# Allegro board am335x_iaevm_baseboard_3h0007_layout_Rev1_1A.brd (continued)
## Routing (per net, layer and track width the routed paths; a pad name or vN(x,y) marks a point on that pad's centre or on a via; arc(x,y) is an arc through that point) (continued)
DDR_D8: length 46.2
  TOP w0.076: v1(97.96,57.44) U31.C8
  TOP w0.121: v1(88.43,66.55) 88.18,66.8 88.18,67.47 86.33,69.32 86.33,70.33 85.95,70.72 85.95,71.02 85.7,71.27 85.7,71.41 R529.2
  BOTTOM w0.076: 100.14,62.84 98.65,62.84 98.39,62.58 98.39,62.08 98.18,61.87 97.07,61.87 96.79,61.59 96.79,61.28 96.94,61.14 96.94,60.49 96.81,60.36 96.11,60.36 95.99,60.24 95.99,59.7 96.11,59.57 96.87,59.57 97,59.45 97,59.18 96.87,59.05 96.05,59.05 95.92,58.93 95.92,58.52 96.05,58.39 96.43,58.39 96.56,58.27 96.56,57.19 96.74,57 97.53,57 v1(97.96,57.44)
  BOTTOM w0.121: v1(88.43,66.55) 88.64,66.34 90.42,66.34 90.63,66.13 96.24,66.13 96.44,66.33 101.89,66.33 102.02,66.2 102.02,59.73 101.89,59.6 100.81,59.6 100.68,59.73 100.68,62.58 100.43,62.84 100.14,62.84
DDR_D9: length 46.2
  TOP w0.076: 100.14,64.48 100.03,64.48 100.01,64.46 96.49,64.46 96.37,64.33 96.37,63.16 96.49,63.03 97.4,63.03 97.52,62.9 97.52,62.67 U31.C2
  TOP w0.121: v1(86.97,70.45) 86.85,70.45 86.47,70.83 86.47,70.84 86.21,71.1 86.21,71.34 85.95,71.6 R530.2 ; 100.14,64.48 100.24,64.48 100.36,64.36 102.74,64.36 102.86,64.49 102.86,65.68 102.74,65.81 101.65,65.81 101.15,66.32 101.15,67.54 101.02,67.66 98.33,67.66 98.2,67.54 98.2,65.91 98.02,65.73 98.02,65.57 97.89,65.45 96.3,65.45 96.18,65.57 96.18,66.2 97,67.03 97,68.43 97.13,68.55 101.13,68.55 101.26,68.68 v1(101.26,69.06)
  BOTTOM w0.121: v1(101.26,69.06) 101.26,69.33 101.13,69.45 95.84,69.45 95.55,69.16 93.32,69.16 92.91,69.16 92.28,69.79 91.48,69.79 89.11,69.79 88.96,69.94 87.87,69.94 87.54,70.27 87.15,70.27 v1(86.97,70.45)
DDR_D10: length 42.5
  TOP w0.076: 100.01,59.41 96.89,59.41 96.76,59.28 U31.D7
  TOP w0.121: v1(88.3,70.4) 87.73,70.4 87.16,70.97 87.16,71.41 86.91,71.67 R531.2 ; 100.01,59.41 101.82,59.41 101.95,59.28 101.95,56.62 102.08,56.49 102.93,56.49 103.05,56.62 103.05,62.62 103.18,62.75 103.48,62.75 103.61,62.87 103.61,66.43 103.48,66.55 102.02,66.55 101.89,66.68 101.89,68.43 102.02,68.55 102.34,68.55 102.46,68.68 102.46,68.88 v1(102.41,68.93)
  BOTTOM w0.121: v1(102.41,68.93) 102.41,69.38 102.28,69.51 101.83,69.51 101.83,69.51 101.66,69.51 101.29,69.89 99.92,69.89 99.73,69.7 95.73,69.7 95.44,69.41 93.22,69.41 93.01,69.41 92.38,70.04 91.58,70.04 89.23,70.04 88.88,70.38 88.62,70.38 88.61,70.4 v1(88.3,70.4)
DDR_D11: length 43.7
  TOP w0.076: v1(97.16,61.44) U31.D3
  LY3 w0.133: v1(85.81,70.09) 85.54,70.09 84.24,71.39 84.24,73.02 84.05,73.21 v1(84.05,73.95)
  BOTTOM w0.076: v1(97.16,61.44) 97.16,60.33 97.43,60.06 100.06,60.06
  BOTTOM w0.121: 100.06,60.06 100.14,59.98 100.14,58.65 100.26,58.52 103.29,58.52 103.42,58.65 103.42,68.49 103.29,68.62 102.72,68.62 102.59,68.49 100.94,68.49 100.81,68.62 100.81,69.08 100.68,69.21 95.94,69.21 95.65,68.92 94.38,68.92 93.43,68.92 92.81,68.92 92.18,69.55 91.38,69.55 89.01,69.55 88.86,69.7 87.73,69.7 87.42,70.01 85.89,70.01 v1(85.81,70.09) ; R532.2 v1(84.05,73.95)
DDR_D12: length 44.2
  TOP w0.076: 100.14,64.24 97.29,64.24 97.16,64.11 v1(97.16,63.84) U31.D1
  TOP w0.121: v1(96.62,65.89) 97.83,65.89 97.95,66.01 97.95,67.79 98.08,67.92 101.27,67.92 101.4,67.79 101.4,66.42 101.76,66.06 102.98,66.06 103.11,65.93 103.11,63.37 102.98,63.24 102.97,63.24 102.85,63.11 102.56,62.82 102.56,60.55 102.43,60.43 100.43,60.43 100.3,60.55 100.3,64.07 100.14,64.24 100.14,64.24 ; v1(88.49,65.89) 88.47,65.89 87.93,66.43 87.93,67.27 85.38,69.82 85.38,69.89 85.37,69.9 85.37,70.27 85.38,70.28 85.38,70.71 v1(85.51,70.84)
  BOTTOM w0.121: v1(88.49,65.89) 89.15,65.89 89.35,66.09 90.32,66.09 90.52,65.89 v1(96.62,65.89) ; R533.2 85.51,74.21 85.51,70.84 v1(85.51,70.84)
DDR_D13: length 46.5
  TOP w0.076: v1(97.16,56.64) U31.D9
  TOP w0.121: v1(100.75,56.68) 100.75,55.79 100.88,55.66 103.67,55.66 103.8,55.79 103.8,61.82 103.92,61.95 104.24,61.95 104.37,62.08 104.37,67.47 104.24,67.6 v1(102.97,67.6)
  LY3 w0.133: v1(87.18,69.48) 87.18,69.72 87.42,69.95 87.42,70.63 87.15,70.9 87.04,70.9 v1(86.65,71.28)
  BOTTOM w0.076: 99.11,56.36 99.19,56.44 99.19,56.83 99.36,57 100.13,57 100.14,57 ; 98.41,56.36 98.33,56.44 98.33,56.81 98.14,57 97.81,57 97.44,56.64 v1(97.16,56.64)
  BOTTOM w0.121: R534.2 86.84,74.65 86.4,74.21 86.4,73.82 86.14,73.57 86.14,71.79 v1(86.65,71.28) ; 100.14,57 100.43,57 v1(100.75,56.68) ; v1(102.97,67.6) 102.97,68.12 102.84,68.24 100.84,68.24 100.12,68.96 96.05,68.96 95.76,68.67 94.48,68.67 93.53,68.67 92.71,68.67 92.08,69.3 91.27,69.3 88.91,69.3 88.76,69.45 87.21,69.45 v1(87.18,69.48) ; 98.41,56.36 98.58,56.19 98.94,56.19 99.11,56.36
DDR_D14: length 40.3
  TOP w0.076: 100.02,60.84 100.02,62.68 99.67,63.03 98.72,63.03 98.36,63.39 U31.B1
  TOP w0.121: v1(101.2,70.66) 101.7,70.66 101.83,70.53 101.83,68.71 101.64,68.53 101.64,66.52 101.86,66.31 103.23,66.31 103.36,66.18 103.36,63.12 103.23,62.99 103.08,62.99 102.95,62.87 102.81,62.72 102.81,60.24 102.68,60.11 100.14,60.11 100.02,60.24 100.02,60.84
  BOTTOM w0.121: R535.2 87.09,72.24 87.09,71.17 87.42,70.84 87.79,70.84 87.79,70.85 88.79,70.85 89.35,70.29 91.68,70.29 91.69,70.29 92.17,70.29 92.49,70.29 92.68,70.09 93.12,69.66 95.06,69.66 95.35,69.95 96.62,69.95 96.75,70.08 96.75,70.73 96.87,70.85 97.26,70.85 97.38,70.73 97.38,70.08 97.51,69.95 97.89,69.95 98.02,70.08 98.02,70.73 98.14,70.85 98.65,70.85 98.78,70.73 98.78,70.08 98.91,69.95 99.22,69.95 99.35,70.08 99.35,70.73 99.48,70.85 101,70.85 v1(101.2,70.66)
DDR_D15: length 40
  TOP w0.076: v1(98.76,56.64) U31.B9
  TOP w0.121: R536.2 90.27,71.6 90.65,71.6 v1(90.97,71.28)
  BOTTOM w0.076: 100.14,57.39 99.38,57.39 99.19,57.21 99.19,57.07 v1(98.76,56.64)
  BOTTOM w0.121: v1(90.97,71.28) 91.22,71.03 92.79,71.03 93.43,70.4 94.28,70.4 94.57,70.69 95.52,70.69 96.43,71.6 101.89,71.6 103.66,69.83 103.66,55.34 103.42,55.09 101.57,55.09 101.45,55.22 101.45,58.1 101.32,58.23 100.49,58.23 100.37,58.1 100.37,57.52 100.24,57.39 100.14,57.39
DDR_DQM0: length 41
  TOP w0.076: 77.91,61.27 77.7,61.06 76.68,61.06 76.54,61.21 v1(76.54,61.44) U8.B3
  TOP w0.121: v1(90.02,67.04) 90.02,67.6 89.57,68.05 89.57,68.43 89.7,68.55 90.14,68.55 90.27,68.68 90.27,68.87 90.14,69 89.7,69 89.57,69.13 89.57,69.92 90.05,70.4 90.46,70.4 90.59,70.27 90.59,69.44 90.72,69.32 90.94,69.32 91.41,69.79 91.41,71.41 91.41,71.41 91.41,71.47 91.15,71.73 91.1,71.73 R16.2 ; v1(76.18,67.15) 76.17,67.16 76.17,68.36 76.05,68.49 75.79,68.49 75.66,68.36 75.66,67.87 75.48,67.68 75.48,66.14 75.67,65.94 77.23,65.94 78.01,65.16 78.01,64.62 78.02,64.62 78.02,64.11 78.14,63.99 78.6,63.99 78.72,63.87 78.72,63.62 78.6,63.5 78.14,63.5 78.02,63.38 78.02,63.14 78.14,63.02 78.6,63.02 78.72,62.9 78.72,62.66 78.6,62.54 78.14,62.54 78.02,62.42 78.02,61.38 77.91,61.27
  BOTTOM w0.121: v1(90.02,67.04) 89.83,66.85 89.5,66.85 89.5,66.84 89.14,66.84 88.69,67.28 86.53,67.28 85.9,67.91 83.9,67.91 80.2,67.91 79.21,66.92 77.68,66.92 77.57,67.03 77.57,67.22 77.44,67.34 77.25,67.34 77.13,67.22 77.13,67.05 77,66.92 76.81,66.92 76.58,67.15 v1(76.18,67.15)
DDR_DQM1: length 46.2
  TOP w0.076: v1(98.76,61.44) U31.B3
  BOTTOM w0.076: v1(98.76,61.44) 99.03,61.44 99.16,61.56 99.16,62.46 99.29,62.58 100.14,62.58
  BOTTOM w0.121: 100.14,62.58 100.26,62.58 100.38,62.46 100.38,58.9 100.51,58.77 102.15,58.77 102.27,58.9 102.27,60.62 102.4,60.74 102.59,60.74 102.72,60.62 102.72,58.9 102.84,58.77 103.03,58.77 103.16,58.9 103.16,67.03 103.03,67.16 102.53,67.16 102.4,67.28 102.4,67.79 102.21,67.98 100.75,67.98 100.74,67.99 100.73,67.99 100.02,68.71 96.15,68.71 95.86,68.42 94.59,68.42 93.63,68.42 92.6,68.42 91.97,69.05 91.05,69.05 88.75,69.05 88.6,69.2 87.53,69.2 87.36,69.03 87,69.03 86.39,69.64 85.32,69.64 85,69.96 R19.2
DDR_DQS0: length 37.8
  TOP w0.076: U8.B7 76.66,59.16 77.78,59.16
  TOP w0.121: v1(79.98,66.65) 79.98,66.2 80.43,65.75 80.43,65.29 80.44,65.28 80.44,65.22 80.62,65.04 80.62,62.07 80.3,61.76 80.3,55.95 79.82,55.47 79.41,55.47 79.29,55.6 79.29,56.11 79.16,56.23 78.28,56.23 78.16,56.36 78.16,57.11 77.91,57.36 77.91,59.03 77.78,59.16 ; R17.2 93.57,71.5 93.18,71.11 93.18,68.99 91.92,67.74 v1(91.92,66.9)
  BOTTOM w0.121: v1(91.92,66.9) 91.54,66.52 90.66,66.52 90.59,66.59 89.03,66.59 88.6,67.03 86.43,67.03 85.79,67.66 81,67.66 v1(79.98,66.65)
DDR_DQS1: length 42.6
  TOP w0.121: U31.B7 98.21,58.64 98.08,58.76 98.08,59.03 98.21,59.16 101.57,59.16 101.7,59.03 101.7,56.36 101.83,56.23 103.17,56.23 103.3,56.36 103.3,62.15 103.7,62.55 103.74,62.55 103.87,62.68 103.87,66.78 103.74,66.91 102.42,66.91 102.15,67.18 102.15,68.02 102.42,68.29 102.72,68.29 102.85,68.42 102.85,69.13 102.65,69.32 v1(102.65,69.76) ; v1(87.6,71.28) 87.86,71.54 R20.2
  BOTTOM w0.121: v1(102.65,69.76) 101.76,69.76 101.64,69.89 101.64,70.97 101.51,71.1 96.63,71.1 95.73,70.2 94.77,70.2 94.48,69.91 93.22,69.91 92.93,70.2 92.59,70.54 92.07,70.54 89.45,70.54 88.89,71.1 88.18,71.1 88,71.28 v1(87.6,71.28)
DDR_DQSN0: length 40.1
  TOP w0.076: 77.9,56.87 U8.A8
  TOP w0.121: 77.9,56.87 77.91,56.86 77.91,55.7 78.4,55.22 79.92,55.22 80.56,55.85 80.56,61.63 80.86,61.94 80.86,65.14 80.69,65.32 80.69,65.39 80.68,65.39 80.68,66.27 80.42,66.52 80.42,66.83 80.09,67.17 79.4,67.17 78.59,67.98 v1(78.58,67.98) ; v1(92.43,67.6) 93.43,68.6 93.43,71 93.82,71.4 93.82,71.4 94.53,72.11 R539.2
  BOTTOM w0.121: v1(78.58,67.98) 78.59,67.98 79.27,68.67 86.2,68.67 86.82,68.05 89.64,68.05 89.9,67.78 90.3,67.78 90.48,67.6 v1(92.43,67.6)
DDR_DQSN1: length 41.4
  TOP w0.121: v1(102.27,70.46) 102.96,70.46 103.1,70.32 103.1,68.17 102.97,68.04 102.53,68.04 102.4,67.92 102.4,67.28 102.53,67.16 103.99,67.16 104.11,67.03 104.11,62.43 103.99,62.31 103.8,62.31 103.55,62.05 103.55,56.11 103.42,55.98 101.45,55.98 101.32,56.11 101.32,58.71 101.19,58.84 100.39,58.84 100.27,58.71 100.27,58.09 100.01,57.84 v1(99.69,57.84) U31.A8 ; R540.2 89.05,72.11 89.29,71.87 v1(89.29,71.53)
  BOTTOM w0.121: v1(89.29,71.53) 89.29,71.12 89.63,70.79 92.69,70.79 93.18,70.3 93.32,70.15 94.38,70.15 94.67,70.45 95.62,70.45 96.52,71.35 101.76,71.35 101.89,71.22 101.89,70.59 102.02,70.46 v1(102.27,70.46)
DDR_ODT: length 65.1
  TOP w0.076: U31.F9 95.16,56.36 ; v1(72.49,56.68) 72.58,56.68 U8.F9
  TOP w0.121: 95.16,56.36 v1(95.16,55.73) ; R543.2 82.78,71.47 83.35,71.47 83.86,70.97 83.86,69.89 87.19,66.56 87.19,66.01 87.38,65.82 87.38,62.96 86.13,61.71 86.13,56.89 85.91,56.66 85.91,55.11 84.72,53.92 84.34,53.92 84.11,53.69 v1(84.11,53.11)
  BOTTOM w0.121: v1(72.49,56.68) 71.73,56.68 71.6,56.55 71.6,51.47 71.73,51.35 83.29,51.35 83.41,51.47 83.41,52.81 83.71,53.11 v1(84.11,53.11) 84.57,53.11 84.81,52.87 84.81,50.71 84.94,50.58 95.35,50.58 95.48,50.71 95.48,54.08 95.6,54.2 95.99,54.2 96.11,54.33 96.11,55.52 95.91,55.73 v1(95.16,55.73)
DDR_RASN: length 63.5
  TOP w0.076: v1(72.54,59.04) U8.F7 ; v1(94.76,59.04) U31.F7
  LY3 w0.133: v1(84.49,57) 84.84,57 85.32,57.47 85.32,58.71 85.13,58.9 84.75,58.9 84.49,59.16 84.49,59.53 84.5,59.54 84.5,59.79 84.68,59.98 84.86,59.98 85.12,60.24 85.12,62.19 85.51,62.58 85.51,66.71 80.62,71.6 80.62,73 79.79,73.82 v1(79.73,73.82)
  BOTTOM w0.076: 90.59,56.79 90.59,57.7 90.72,57.82 94.17,57.82 94.33,57.99 94.33,58.91 94.46,59.04 v1(94.76,59.04) ; v1(72.54,59.04) 72.24,59.04 72.11,59.16 72.11,60.15 72.24,60.27 73.63,60.27 73.76,60.15 73.76,58.9 73.89,58.77 76.05,58.77 77.12,57.7 77.91,57.7
  BOTTOM w0.121: v1(79.73,73.82) 79.79,73.82 80.24,74.27 R14.2 ; 84.49,57 v1(84.49,57) ; 84.49,57 85.37,57 85.38,56.99 86.49,56.99 86.68,56.8 86.72,56.8 86.75,56.77 87.02,56.77 87.29,56.5 87.29,54.33 87.41,54.2 92.11,54.2 92.24,54.33 92.24,54.59 92.11,54.72 90.87,54.72 90.59,54.99 90.59,56.79 ; 84.49,57 84.49,57.19 84.37,57.32 83.99,57.32 83.79,57.12 83.61,57.12 83.41,57.32 83.16,57.32 83.04,57.2 83.04,56.92 82.92,56.8 82.68,56.8 82.56,56.92 82.56,57.2 82.44,57.32 82.2,57.32 82.08,57.2 82.08,56.92 81.96,56.8 81.72,56.8 81.6,56.92 81.6,57.2 81.48,57.32 81.23,57.32 81.11,57.2 81.11,56.92 80.99,56.8 80.75,56.8 80.63,56.92 80.63,57.2 80.51,57.32 80.27,57.32 80.15,57.2 80.15,56.92 80.03,56.8 79.79,56.8 79.67,56.92 79.67,57.2 79.55,57.32 79.3,57.32 79.18,57.2 79.18,56.92 79.06,56.8 78.58,56.8 78.33,57.05 78.33,57.5 78.13,57.7 77.91,57.7
DDR_VREF: length 67
  TOP w0.076: 95.16,65.16 95.16,63.61 95.29,63.49 95.4,63.49 95.96,62.93 U31.E2 v1(96.36,62.24) ; v1(74.14,62.24) U8.E2 73.75,62.64 74.21,63.09 74.21,64.81 74.08,64.93 73.06,64.93 72.94,65.06 72.94,65.16
  TOP w0.102: v2(84.2,80.2) U2.J4
  TOP w0.121: v1(73.44,67.16) 72.94,66.65 72.94,65.16 ; 95.16,65.16 95.16,66.03 94.28,66.91 94.28,66.96 R542.2
  BOTTOM w0.076: v1(74.14,62.24) 74.55,61.82 77.57,61.82 77.89,61.5 77.91,61.5 ; 89.24,59.41 92.8,59.41 92.94,59.56 94.67,59.56 95.16,60.04 95.16,61.7 95.33,61.87 95.99,61.87 v1(96.36,62.24)
  BOTTOM w0.102: 77.19,80.44 77.96,81.21 79.53,81.21 79.7,81.38 80.43,81.38 81.19,80.62 83.52,80.62 83.94,80.2 v2(84.2,80.2) 84.59,80.2 R541.2
  BOTTOM w0.121: 89.24,59.41 89.02,59.41 88.17,60.26 88.17,60.48 87.66,60.99 82.47,60.99 81.71,61.75 81.02,61.75 80.77,61.49 79.22,61.49 79.09,61.63 78.72,61.63 78.59,61.5 77.91,61.5 ; v1(73.44,67.16) 71.83,68.77 71.83,73.86 72.23,74.27 72.23,77.25 71.6,77.88 71.6,78.67 72.79,79.85 74.01,79.85 74.06,79.9 76.16,79.9 76.36,80.09 76.84,80.09 77.18,80.44 77.19,80.44
DDR_WEN: length 60.6
  TOP w0.076: v1(72.54,61.44) 72.49,61.39 72.49,60.87 72.59,60.77 73.55,60.77 73.66,60.87 73.66,61.06 73.53,61.19 73.06,61.19 72.94,61.31 U8.F3 ; U31.F3 v1(95.56,61.44)
  TOP w0.121: R15.2 73.57,71.56 75.37,69.77 77.47,69.77 79.67,67.56 79.82,67.42 80.19,67.42 80.67,66.93 80.67,66.63 81.57,65.73 81.57,65.32 81.55,65.31 81.55,61.25 81.32,61.01 v1(81.32,61)
  BOTTOM w0.076: 89.3,57.31 89.59,57.31 89.7,57.43 89.7,59.09 89.83,59.22 90.98,59.22 91.11,59.09 91.11,58.79 91.24,58.67 91.71,58.67 91.78,58.74 92.11,58.74 92.18,58.67 92.51,58.67 92.73,58.88 92.73,59.12 93.01,59.4 93.31,59.4 93.46,59.26 93.66,59.26 93.81,59.4 94.11,59.4 94.26,59.26 94.46,59.26 94.61,59.4 95.73,59.4 95.83,59.5 95.83,61.33 95.73,61.44 v1(95.56,61.44) ; 77.91,61.06 77.91,59.85 77.79,59.73 77.63,59.73 77.51,59.85 77.51,60.74 77.38,60.87 77.19,60.87 77.08,60.76 77.08,59.85 76.95,59.73 76.36,59.73 76.24,59.85 76.24,60.04 76.11,60.17 75.92,60.17 75.79,60.04 75.79,59.85 75.67,59.73 74.97,59.73 74.84,59.85 74.84,60.18 74.8,60.22 74.8,60.25 74.5,60.55 74.5,61.59 74.29,61.8 73.82,61.8 73.7,61.93 73.7,62.46 73.57,62.58 73.38,62.58 73.25,62.46 73.25,61.31 73.13,61.19 72.78,61.19 v1(72.54,61.44)
  BOTTOM w0.121: 77.91,61.06 78.04,61.19 78.28,61.19 78.52,60.94 78.52,60.35 78.7,60.17 79.16,60.17 79.29,60.3 79.29,60.87 79.42,61 80.04,61 80.17,60.87 80.17,60.55 80.3,60.43 80.49,60.43 80.62,60.55 80.62,60.87 80.75,61 v1(81.32,61) 81.32,60.56 81.44,60.43 86.97,60.43 87.55,59.86 88.22,59.86 88.55,59.53 88.55,59.25 89.13,58.68 89.13,57.49 89.3,57.31
EMU2: length 53.9
  TOP w0.121: R76.1 66.18,94.02 65.73,94.46 64.94,94.46 64.12,95.29 60.34,95.29 59.49,94.44 57.37,94.44 56.03,93.11 48.22,93.11 47.24,92.13 32.7,92.13 31.75,91.19 27.94,91.19 26.58,89.83 21.63,89.83 v1(21.12,89.32) ; 24,86.65 v1(22.14,86.65)
  BOTTOM w0.121: v1(21.12,89.32) 21.12,87.13 21.6,86.65 v1(22.14,86.65)
EMU3: length 40.2
  TOP w0.121: J2.18 31.66,86.65 32.04,87.03 32.04,89.78 33.27,91 35.21,91 35.62,90.59 46.9,90.59 48.68,92.37 57.23,92.37 57.31,92.45 61.59,92.45 62.71,93.57 63.48,93.57 R77.1
EMU4: length 62.5
  TOP w0.121: 24,85.38 v1(22.14,85.38) ; v1(20.1,89.32) 20.87,88.56 26.2,88.56 27.47,89.83 31.53,89.83 32.96,91.25 47.19,91.25 48.55,92.61 56.24,92.61 57.19,93.57 59.22,93.57 59.73,93.06 61.31,93.06 62.39,94.14 63.86,94.14 64.57,93.44 64.96,93.44 65.65,92.75 67.66,92.75 68.42,91.99 70.52,91.99 R78.1
  BOTTOM w0.121: v1(20.1,89.32) 20.1,86.65 21.37,85.38 v1(22.14,85.38)
EMU_RSTN: length 6.4
  TOP w0.121: R517.1 v1(22.14,87.92) 24,87.92
  BOTTOM w0.121: v1(22.14,87.92) 22.77,87.92 23.15,87.54 23.15,87.03 23.53,86.65 C260.1
ENZ_KALDO_1P8V: length 9.6
  TOP w0.102: U2.B4 78.64,80.24 78.64,79.72 78.33,79.41 77.76,79.41 77.34,79.83
  TOP w0.121: 77.34,79.83 76.63,79.83 75.97,79.17 72,79.17 R48.2
EXP0_P25: length 5.4
  BOTTOM w0.121: R178.2 132.45,92.79 133.86,92.79 133.93,92.72 134.63,92.72 J3.25
EXP3_P9: length 2.8
  BOTTOM w0.121: J6.9 TP35.1
EXP_ECAP0_IN_PWM0_OUT: length 4.1
  TOP w0.121: R210.2 v1(74.33,134.02)
  BOTTOM w0.121: v1(74.33,134.02) 73.57,134.78 J5.19
EXP_GPMC_ADVN_ALE: length 17.1
  TOP w0.121: R182.1 138.21,97.45 138.21,96.3 137.18,95.27 132.59,95.27 131.82,94.49 131.82,93.97 131.61,93.77 129.81,93.77 128.8,94.78 127.81,94.78 126.93,93.89 J4.26
EXP_GPMC_BE0N_CLE: length 15.7
  TOP w0.121: R184.1 138.08,94.78 132.8,94.78 132.31,94.29 132.31,93.58 131.61,92.87 v1(130.26,92.87)
  BOTTOM w0.121: J4.28 126.66,91.35 127.67,92.37 129.4,92.37 129.78,92.75 130.13,92.75 v1(130.26,92.87)
EXP_GPMC_BE1N: length 8.8
  TOP w0.121: J5.2 99.27,139.61 99.4,139.74 99.4,141.13 99.27,141.26 96.56,141.26 96.43,141.39 R186.1
EXP_GPMC_CLK: length 8.8
  TOP w0.121: 119.93,95.03 123.55,95.03 124.04,95.52 126.4,95.52 127.31,96.43 J4.23
EXP_GPMC_CS0N: length 13.1
  TOP w0.121: J4.25 129.33,93.89 129.7,93.52 131.9,93.52 132.06,93.68 132.06,94.39 132.69,95.02 137.31,95.02 138.47,96.18 138.47,96.43 R183.1
EXP_GPMC_CS3N: length 8.8
  TOP w0.121: R187.1 v1(93.89,142)
  BOTTOM w0.121: J5.4 93.89,140.68 93.76,140.8 92.14,140.8 92.01,140.93 92.01,142.99 92.14,143.12 93.76,143.12 93.89,142.99 v1(93.89,142)
EXP_GPMC_OEN_REN: length 79.4
  TOP w0.121: v1(137.58,104.56) 137.96,104.18 R189.1 ; J5.6 92.61,138.35 97.42,138.35 97.54,138.47 99.48,138.47 100.06,137.88 106.29,137.88 109.89,134.28 118.78,134.28 120.18,132.88 129.83,132.88 131.61,131.1 134.69,131.1 136.73,129.06 137.1,129.06 137.64,128.52 137.64,128.06 138.03,127.67 v1(139.23,127.67)
  BOTTOM w0.121: v1(137.58,104.56) 137.58,104.81 138.34,105.57 138.34,109.18 137.45,110.06 137.45,117.59 138.09,118.23 138.09,126.23 138.34,126.48 138.34,126.78 v1(139.23,127.67)
EXP_GPMC_WAIT: length 13.9
  TOP w0.121: J4.19 130.21,101.51 132.24,103.54 132.24,104.43 132.75,104.94 136.17,104.94 137.5,103.61 138.61,103.61 139.1,103.11 R179.1
EXP_GPMC_WEN: length 81.1
  TOP w0.121: R191.1 v1(137.58,105.57) ; v1(138.21,128.43) 138.21,128.43 137.96,128.69 137.96,128.69 137.34,129.31 136.83,129.31 134.78,131.36 131.74,131.36 129.89,133.2 120.37,133.2 118.97,134.6 110.03,134.6 106.46,138.16 100.57,138.16 99.88,138.85 97.57,138.85 97.32,138.59 95.67,138.59 95.29,138.98 95.29,140.12 94.78,140.63 89.83,140.63 J5.8
  BOTTOM w0.121: v1(137.58,105.57) 137.58,106.08 138.09,106.59 138.09,109.08 137.21,109.96 137.21,117.7 137.84,118.33 137.84,126.33 138.09,126.58 138.09,127.55 138.21,127.67 v1(138.21,128.43)
EXP_GPMC_WPN: length 12.7
  TOP w0.121: R180.1 137.05,101.51 136.17,102.4 132.89,102.4 130.55,100.05 129.47,98.97 J4.21
EXP_I2C1_SCL: length 2.1
  TOP w0.121: R176.1 131.36,96.43 J3.24
EXP_I2C1_SDA: length 102.3
  TOP w0.121: v1(68.43,94.78) R177.2
  LY3 w0.133: v1(120.48,111.55) 118.81,113.22 96.25,113.22 95.49,113.98 81.8,113.98 81.39,113.58 77.13,113.58 76.49,112.94 68.9,112.94 68.36,112.41 v1(68.36,112.38)
  BOTTOM w0.121: v1(68.43,94.78) 68.42,94.78 67.89,95.31 67.89,103.8 68.36,104.27 v1(68.36,112.38) ; v1(120.48,111.55) 120.48,99.73 122.08,98.13 122.08,97.7 123.13,96.66 124.52,96.66 125.25,97.38 133.65,97.38 134.6,96.43 J3.23
EXP_MII1_COL: length 71.5
  TOP w0.121: R231.1 81.83,100.67 v1(82.28,101.13) ; J5.34 55.79,139.64 56.71,140.56 82.98,140.56 83.23,140.81 83.95,140.81 v1(84.17,141.03)
  BOTTOM w0.121: v1(82.28,101.13) 82.28,101.18 81.48,101.98 81.48,116.81 82.13,117.46 82.13,120.77 84.05,122.69 84.05,130.38 84.68,131.01 84.68,140 84.57,140.11 84.57,140.63 v1(84.17,141.03)
EXP_MII1_CRS: length 6.9
  TOP w0.121: R235.1 v1(52.21,134.15)
  BOTTOM w0.121: v1(52.21,134.15) 52.21,138.57 J5.36
EXP_MII1_MDIO_CLK: length 3.6
  TOP w0.121: R195.2 87.29,136.05 J5.9
EXP_MII1_MDIO_DATA: length 3.3
  TOP w0.121: R192.2 88.43,136.69 J5.7
EXP_MII1_REFCLK: length 79.5
  TOP w0.121: v1(85.78,141.24) 86.92,141.24 87.34,140.82 87.34,138.8 87.8,138.34 91.62,138.34 92.89,137.07 J5.3
  BOTTOM w0.121: R188.2 84.24,103.8 85,104.56 85,118.6 85.13,118.73 85.56,118.73 85.69,118.6 85.69,105.27 85.81,105.14 86.15,105.14 86.28,105.27 86.28,123.14 86.27,123.15 86.27,133.77 85.25,134.78 85.25,140.72 v1(85.78,141.24)
EXP_MII1_RXCLK: length 79.5
  TOP w0.121: R162.1 86.65,101.08 88.29,102.71 88.29,105.97 89.96,107.64 99.55,107.64 99.76,107.86 108.14,107.86 108.6,107.4 119.75,107.4 119.87,107.28 119.87,107.1 120,106.97 123.96,106.97 124.09,106.84 124.09,106.54 123.96,106.41 121.3,106.41 121.17,106.29 121.17,105.9 121.3,105.78 124.63,105.78 124.75,105.9 124.75,107.43 124.63,107.56 120.66,107.56 120.53,107.68 120.53,108.09 120.66,108.22 129.37,108.22 129.5,108.34 129.5,110.65 129.63,110.78 131.13,110.78 131.25,110.91 131.25,117.74 131.38,117.87 133.13,117.87 133.26,117.74 J3.8
EXP_MII1_RXD0: length 79.4
  TOP w0.121: v1(89.89,99.61) 89.44,99.15 89.44,98.32 R190.2
  BOTTOM w0.121: J5.5 91.35,138.39 91.48,138.52 97.7,138.52 97.83,138.39 97.83,136.1 97.7,135.98 91.4,135.98 91.27,135.85 91.27,135.39 91.4,135.27 97.7,135.27 97.83,135.14 97.83,134.66 97.7,134.53 91.96,134.53 91.83,134.4 91.83,133.87 91.96,133.74 97.6,133.74 97.73,133.62 97.73,133.14 97.6,133.02 93.71,133.02 93.04,132.35 93.04,122.3 89.37,118.63 89.37,105.98 89.14,105.75 89.14,99.83 89.37,99.61 v1(89.89,99.61)
EXP_MII1_RXD1: length 79.5
  TOP w0.121: v1(88.68,99.22) 88.81,99.35 88.81,101.64 89.09,101.92 89.09,105.72 89.63,106.26 93.03,106.26 93.25,106.48 103.18,106.48 103.75,107.05 107.76,107.05 108.44,106.36 113.68,106.36 113.8,106.23 113.8,103.29 113.93,103.16 114.24,103.16 114.36,103.29 114.36,106.29 114.49,106.41 114.82,106.41 114.95,106.29 114.95,103.29 115.07,103.16 115.79,103.16 115.92,103.29 115.92,104.23 116.05,104.35 117.39,104.35 117.51,104.23 117.51,103.29 117.64,103.16 118.38,103.16 118.5,103.29 118.5,104.18 118.63,104.3 120.46,104.3 120.59,104.18 120.59,103.97 120.46,103.85 119.34,103.85 119.21,103.72 119.21,103.29 119.34,103.16 124.57,103.16 124.7,103.29 124.7,103.72 124.57,103.85 v1(121.32,103.85)
  BOTTOM w0.121: v1(121.32,103.85) 121.45,103.72 121.45,101.69 123.22,99.92 132.31,99.92 J3.22 ; R185.1 88.05,98.59 v1(88.68,99.22)
EXP_MII1_RXD2: length 79.2
  TOP w0.121: v1(88.25,99.91) 88.53,100.19 88.53,101.89 88.78,102.15 88.78,105.77 90.16,107.14 91.31,107.14 91.72,106.73 99.34,106.73 99.97,107.36 107.79,107.36 108.4,106.75 115.79,106.75 115.92,106.63 115.92,104.91 116.05,104.79 116.55,104.79 116.67,104.91 116.67,106.67 116.8,106.79 117.44,106.79 117.56,106.67 117.56,104.91 117.69,104.79 123.99,104.79 124.27,105.07 129.12,105.07 129.25,104.94 129.25,103.62 129.37,103.49 130.19,103.49 130.31,103.62 130.31,109.64 130.44,109.77 131.23,109.77 131.36,109.64 131.36,106 131.48,105.87 132.07,105.87 132.19,106 132.19,113.14 J3.10
  BOTTOM w0.121: v1(88.25,99.91) 87.54,99.91 86.91,99.27 86.91,98.82 87.03,98.69 R164.1
EXP_MII1_RXD3: length 79.6
  TOP w0.121: J3.4 134.25,120.84 134.25,115.22 134.12,115.1 132.07,115.1 131.95,114.97 131.95,110.25 131.82,110.12 130.26,110.12 130.06,109.92 130.06,105.47 129.91,105.32 120.86,105.32 120.74,105.45 120.74,106.44 120.61,106.56 120.28,106.56 120.15,106.44 120.15,105.16 120.03,105.03 119.7,105.03 119.57,105.16 119.57,106.74 119.44,106.87 119.11,106.87 118.98,106.74 118.98,105.16 118.86,105.03 118.59,105.03 118.46,105.16 118.46,107.02 118.33,107.15 108.37,107.15 107.91,107.61 99.87,107.61 99.23,106.97 91.93,106.97 91.52,107.39 90.06,107.39 88.54,105.87 88.54,102.61 87.79,101.86 87.79,99.53 87.9,99.41 87.9,98.42 R158.1
EXP_MII1_RXDV: length 79.5
  TOP w0.121: R168.1 83.17,98.13 82.23,99.07 82.23,100.45 84.14,102.36 84.14,104.71 87.46,108.04 88.54,108.04 89.38,108.88 97.5,108.88 99.02,110.4 107.23,110.4 107.35,110.53 107.35,110.98 107.23,111.11 101.28,111.11 101.15,111.24 101.15,111.86 101.28,111.99 115.28,111.99 115.4,111.86 115.4,111.48 115.53,111.35 116.12,111.35 116.24,111.48 116.24,111.86 116.37,111.99 117.11,111.99 117.23,111.86 117.23,111.54 117.36,111.42 118.25,111.42 118.38,111.54 118.38,111.86 118.5,111.99 119.04,111.99 119.16,111.86 119.16,111.57 119.29,111.44 119.9,111.44 120.03,111.57 120.03,111.86 120.15,111.99 122.88,111.99 v1(122.91,111.96)
  BOTTOM w0.121: v1(122.91,111.96) 123.39,111.96 124.69,110.66 124.69,108 125.01,107.68 131.81,107.68 J3.14
EXP_MII1_RXERR: length 64.9
  TOP w0.121: v1(52.18,108.67) 78.11,108.67 82.22,104.56 R237.1
  BOTTOM w0.121: J5.38 51.73,138.59 51.73,135.9 51.04,135.22 51.04,117.66 51.8,116.9 51.8,109.79 52.18,109.41 v1(52.18,108.67)
EXP_MII1_TXCLK: length 79.7
  TOP w0.121: R160.1 85.13,98.43 85.13,102.3 87.09,104.26 87.09,105.89 89.58,108.38 98.83,108.38 99.11,108.66 108.32,108.66 108.45,108.79 108.45,110.4 108.58,110.53 129.07,110.53 129.2,110.65 129.2,117.87 129.32,117.99 129.96,117.99 130.09,117.87 130.09,111.34 130.21,111.21 130.75,111.21 130.87,111.34 130.87,119.16 131,119.29 J3.6
EXP_MII1_TXD0: length 79.4
  TOP w0.121: R174.1 85.64,102.45 87.34,104.15 87.34,105.75 89.72,108.13 99.12,108.13 99.4,108.41 111.52,108.41 111.64,108.54 111.64,108.95 111.52,109.08 108.83,109.08 108.7,109.21 108.7,109.77 108.83,109.89 112.56,109.89 112.69,109.77 112.69,108.94 112.81,108.81 117.51,108.81 117.64,108.94 117.64,109.26 117.51,109.38 113.35,109.38 113.22,109.51 113.22,109.89 113.35,110.02 v1(123.13,110.02)
  BOTTOM w0.121: J3.20 132.31,102.46 122.76,102.46 122.26,102.95 122.26,109.74 122.54,110.02 v1(123.13,110.02)
EXP_MII1_TXD1: length 79.5
  TOP w0.121: v1(123.13,109.18) 124.01,109.18 124.63,109.18 124.76,109.05 124.76,108.67 124.63,108.55 122.52,108.55 122.39,108.67 122.39,109.54 122.26,109.66 118.15,109.66 118.02,109.54 118.02,109.13 118.15,109 120.15,109 120.28,108.88 120.28,107.83 120.15,107.71 119.75,107.71 119.62,107.83 119.62,108.24 119.49,108.37 119.19,108.37 119.06,108.24 119.06,107.83 118.93,107.71 118.59,107.71 118.46,107.83 118.46,108.29 118.33,108.42 117.71,108.42 117.58,108.29 117.58,107.81 117.45,107.68 116.14,107.68 116.01,107.81 116.01,108.42 115.89,108.55 115.17,108.55 115.04,108.42 115.04,107.86 114.91,107.73 114.51,107.73 114.39,107.86 114.39,108.27 114.26,108.39 113.65,108.39 113.52,108.27 113.52,107.86 113.4,107.73 112.86,107.73 112.74,107.86 112.74,108.27 112.61,108.39 112.15,108.39 112.03,108.27 112.03,107.86 111.9,107.73 111.42,107.73 111.29,107.86 111.29,108.01 111.16,108.14 110.6,108.14 110.48,108.01 110.48,107.86 110.35,107.73 109.99,107.73 109.87,107.86 109.87,108.01 109.74,108.14 109.36,108.14 109.23,108.01 109.23,107.86 109.1,107.73 108.7,107.73 108.27,108.16 99.68,108.16 99.4,107.89 89.85,107.89 89.42,107.45 89.39,107.45 87.84,105.9 87.84,103.9 86.9,102.96 86.9,102.02 86.14,101.26 86.14,98.82 86.52,98.44 R172.1
  BOTTOM w0.121: v1(123.13,109.18) 123.15,109.16 123.15,103.17 123.56,102.75 131.96,102.75 J3.18
EXP_MII1_TXD2: length 79.7
  TOP w0.121: R166.1 89.19,98.56 89.19,99.68 89.37,99.86 89.37,105.65 89.7,105.98 93.1,105.98 93.33,106.21 103.42,106.21 103.96,106.75 107.55,106.75 108.19,106.11 113.4,106.11 113.52,105.98 113.52,102.96 113.65,102.83 116.87,102.83 117,102.7 117,101.7 117.13,101.58 123.68,101.58 123.81,101.7 123.81,102.07 123.68,102.2 117.84,102.2 117.72,102.32 117.72,102.76 117.84,102.89 130.24,102.89 130.99,103.63 130.99,104.55 132.07,105.62 134.17,105.62 134.48,105.93 134.48,111.34 134.15,111.67 J3.12
EXP_MII1_TXD3: length 79.3
  TOP w0.121: R170.1 84.42,101.74 84.42,104.42 87.75,107.76 88.61,107.76 89.48,108.63 98.26,108.63 98.68,109.05 108.08,109.05 108.2,109.18 108.2,109.43 108.08,109.56 99.63,109.56 99.5,109.69 99.5,109.99 99.63,110.12 108.08,110.12 108.2,110.25 108.2,110.98 108.33,111.11 121.9,111.11 122,111.2 v1(122.88,111.2)
  BOTTOM w0.121: J3.16 132.09,105.42 125.47,105.42 124.44,106.44 124.44,110.25 123.49,111.2 v1(122.88,111.2)
EXP_MII1_TXEN: length 79.6
  TOP w0.121: R238.1 84.37,98.87 84.05,99.18 84.05,100.23 84.75,100.93 84.75,102.83 85.41,103.49 v1(85.41,104.05) ; v1(86.52,135.29) 78.98,135.29 78.46,134.77 65.85,134.77 64.36,136.26 64.36,137.46 63.37,138.45 49.35,138.45 48.2,139.61 J5.40
  BOTTOM w0.121: v1(86.52,135.29) 86.52,105.17 v1(85.41,104.05)
EXP_MMC0_CLK: length 3
  BOTTOM w0.121: J5.12 83.6,139.74 R197.1
EXP_MMC0_CMD: length 2.9
  BOTTOM w0.121: R200.1 J5.14
EXP_MMC0_DAT0: length 2.8
  BOTTOM w0.121: J5.16 R204.1
EXP_MMC0_DAT1: length 2.8
  BOTTOM w0.121: R212.1 J5.22
EXP_MMC0_DAT2: length 2.8
  BOTTOM w0.121: J5.24 R215.1
EXP_MMC0_DAT3: length 3.2
  BOTTOM w0.121: R219.1 66.97,140.63 J5.26
EXP_MMC1_CLK: length 49.2
  TOP w0.121: v1(137.36,91.73) 136.94,91.73 136.69,91.47 136.69,90.86 136.29,90.46 132.89,90.46 132.01,91.35 129.43,91.35 128.55,90.46 125.13,90.46 123.6,91.99 117.42,91.99 115.54,90.11 108.34,90.11 108.34,90.11 106.62,90.11 106.62,90.11 102.4,90.11 100.88,88.58 R175.2
  BOTTOM w0.121: v1(137.36,91.73) 137.38,91.75 137.38,97.39 J3.21
EXP_MMC1_CMD: length 40.2
  TOP w0.121: v1(123.48,97.39) 123.48,97.38 121.64,95.54 118.2,95.54 117.36,96.38 103.84,96.38 102.76,95.3 102.04,94.58 102.04,94.22 101.36,93.53 101.36,92.77 R173.2
  BOTTOM w0.121: J3.19 134.21,99.92 134.21,98.58 133.51,97.87 123.97,97.87 v1(123.48,97.39)
EXP_MMC1_DAT0: length 5.1
  TOP w0.121: R171.2 v1(137.58,106.84)
  BOTTOM w0.121: J3.17 136.94,105.19 136.94,106.21 v1(137.58,106.84)
EXP_MMC1_DAT1: length 4
  TOP w0.121: R169.2 137.45,108.24 J3.15
EXP_MMC1_DAT2: length 3.5
  TOP w0.121: R167.2 136.31,109.64 J3.13
EXP_MMC1_DAT3: length 3.6
  TOP w0.121: J3.11 137.2,111.67 137.96,110.91 R165.2
EXP_MMC1_DAT4: length 4.1
  TOP w0.121: R163.2 137.07,114.21 J3.9
EXP_MMC1_DAT5: length 4.6
  TOP w0.121: R161.2 137.2,115.48 137.07,115.48 J3.7
EXP_MMC1_DAT6: length 5.7
  TOP w0.121: R159.2 137.1,116.98 137.1,117.99 J3.5
EXP_MMC1_DAT7: length 7
  TOP w0.121: J3.3 135.8,121.7 137.77,119.73 137.77,117.58 R157.2
EXP_PB_POWERON: length 192.8
  TOP w0.203: v1(155.46,123.02) 155.26,123.23 129.93,123.23 v1(129.35,122.64) ; v1(96.71,53.12) 97.38,53.12 98.31,54.05 100.28,54.05 100.34,53.99 117.03,53.99 120.51,57.47 121.79,57.47 122.94,58.62 128.89,58.62 128.96,58.55 131.39,58.55 132.46,57.48 141.39,57.48 142.24,58.33 150.66,58.33 151.68,57.31 v1(158.15,57.31)
  BOTTOM w0.203: v1(155.46,123.02) 155.46,98.87 157.9,96.43 157.9,57.57 v1(158.15,57.31) ; J4.12 126.73,110.58 128.99,110.58 129.35,110.93 v1(129.35,122.64) ; R63.2 87.79,48.23 89.7,50.14 95.92,50.14 96.71,50.93 v1(96.71,53.12)
EXP_SPI0_CLK: length 105.2
  TOP w0.121: J5.13 81.19,138.34 81,138.53 80.24,138.53 80.05,138.34 80.05,136.37 79.92,136.24 79.35,136.24 79.22,136.12 79.22,136.02 78.74,135.54 78.73,135.54 78.67,135.48 78.04,135.48 77.91,135.61 77.91,136.34 77.63,136.62 77.63,137.89 77.76,138.02 79.35,138.02 79.48,138.15 79.48,138.47 79.35,138.59 77.06,138.59 76.94,138.47 76.94,138.39 76.82,138.27 76.58,138.27 76.46,138.39 76.46,138.47 76.33,138.59 76.09,138.59 75.97,138.47 75.97,138.39 75.85,138.27 75.61,138.27 75.49,138.39 75.49,138.47 75.37,138.59 75.13,138.59 75.01,138.47 75.01,138.39 74.89,138.27 74.65,138.27 74.52,138.39 74.52,138.47 74.4,138.59 74.16,138.59 74.04,138.47 74.04,138.39 73.92,138.27 73.68,138.27 73.56,138.39 73.56,138.47 73.44,138.59 73.2,138.59 73.08,138.47 73.08,138.39 72.96,138.27 72.71,138.27 72.59,138.39 72.59,138.47 72.47,138.59 72.23,138.59 72.11,138.47 72.11,138.39 71.99,138.27 71.75,138.27 71.63,138.39 71.63,138.47 71.51,138.59 71.27,138.59 71.15,138.47 71.15,138.39 71.03,138.27 70.78,138.27 70.66,138.39 70.66,138.47 70.54,138.59 70.3,138.59 70.18,138.47 70.18,138.39 70.06,138.27 69.82,138.27 69.7,138.39 69.7,138.47 69.58,138.59 69.34,138.59 69.22,138.47 69.22,138.39 69.1,138.27 68.85,138.27 68.73,138.39 68.73,138.47 68.61,138.59 68.37,138.59 68.25,138.47 68.25,138.39 68.13,138.27 67.89,138.27 67.77,138.39 67.77,138.47 67.65,138.59 67.41,138.59 67.29,138.47 67.29,138.39 67.17,138.27 66.92,138.27 66.8,138.39 66.8,138.47 66.68,138.59 66.44,138.59 66.32,138.47 66.32,138.39 66.2,138.27 65.96,138.27 65.84,138.39 65.84,138.47 65.72,138.59 64.36,138.59 64.24,138.47 64.24,138.02 64.36,137.9 64.87,137.9 65,137.77 65,136.68 65.04,136.64 65.04,136.27 65.48,135.83 v1(65.48,135.77) ; v1(70.55,95.05) 70.52,95.02 R201.2
  BOTTOM w0.121: v1(70.55,95.05) 70.55,95.59 70.25,95.9 70.25,97.47 69.96,97.75 69.96,100.04 69.59,100.41 69.59,102.63 70.34,103.39 70.34,105.88 69.44,106.78 69.44,117.2 64.63,122.01 63.49,122.01 62.78,122.71 62.78,124.53 63.44,125.19 63.44,129.22 63.56,129.34 65,129.34 65.12,129.46 65.12,129.7 65,129.82 62.65,129.82 62.52,129.95 62.52,130.17 62.65,130.3 65,130.3 65.12,130.42 65.12,130.66 65,130.78 62.52,130.78 62.39,130.91 62.39,131.14 62.52,131.27 65,131.27 65.12,131.39 65.12,131.63 65,131.75 62.58,131.75 62.46,131.88 62.46,132.11 62.58,132.23 65,132.23 65.12,132.35 65.12,132.59 65,132.71 62.84,132.71 62.71,132.84 62.71,133.07 62.84,133.2 65,133.2 65.12,133.32 65.12,133.56 65,133.68 63.56,133.68 63.44,133.8 63.44,134.08 65.13,135.77 v1(65.48,135.77)
EXP_SPI0_CS1: length 59.3
  TOP w0.121: v1(72.05,92.87) 71.67,93.26 71.28,93.26 ; v1(66.51,135.93) 67.14,136.56 67.14,137.55 67.61,138.02 75.16,138.02 J5.17
  BOTTOM w0.121: v1(66.51,135.93) 65.37,134.78 65.37,133.29 65.63,133.02 65.63,124.44 66.23,123.84 66.23,121.02 69.69,117.56 69.69,107.04 70.59,106.14 70.59,103.1 69.83,102.34 69.83,100.51 70.21,100.14 70.21,98.24 70.52,97.93 70.52,95.97 72.05,94.45 v1(72.05,92.87)
EXP_SPI0_D0: length 4.5
  TOP w0.121: v1(79.18,134.78) 79.16,134.78 R205.2
  BOTTOM w0.121: J5.15 79.06,137.07 79.18,136.94 79.18,135.8 79.06,135.67 78.65,135.67 78.52,135.55 78.52,135.29 78.65,135.17 79.06,135.17 79.18,135.04 v1(79.18,134.78)
EXP_UART0_CTSN: length 39.6
  TOP w0.121: v1(77.47,136.16) 77.43,136.12 71.98,136.12 J5.21 ; v1(79.78,105.55) 79.78,105.29 79.79,105.29 R213.2
  BOTTOM w0.121: v1(77.47,136.16) 77.14,135.84 77.14,133.75 78.33,132.56 78.33,122.02 78.88,121.46 78.88,107.72 79.78,106.82 v1(79.78,105.55)
EXP_UART0_RTSN: length 47.3
  TOP w0.121: v1(80.24,100.29) 80.68,99.85 R216.2 ; J5.23 69.84,135.72 76.05,135.72 76.56,135.22 v1(77.59,135.22)
  BOTTOM w0.121: v1(80.24,100.29) 80.24,100.31 80.24,100.31 80.24,103.6 79.57,104.27 79.57,104.81 79.77,105.01 79.92,105.01 80.22,105.31 80.22,106.73 79.13,107.82 79.13,121.83 78.58,122.39 78.58,132.75 77.48,133.84 77.48,135.11 v1(77.59,135.22)
EXP_UART0_RXD: length 52.1
  TOP w0.121: J5.25 65.95,135.72 66.45,135.22 v1(75.93,135.22) ; R220.2 80.65,98.62 v1(80.65,98.75)
  BOTTOM w0.121: v1(75.93,135.22) 76.72,134.43 76.72,129.48 76.05,128.82 76.05,124.25 76.68,123.62 76.68,120.97 78.64,119.02 78.64,107.62 79.34,106.91 79.34,105.05 79.33,105.03 79.33,103.75 79.99,103.09 79.99,101.05 79.71,100.77 79.71,98.94 79.9,98.75 v1(80.65,98.75)
EXP_UART0_TXD: length 44.4
  TOP w0.121: R222.2 71.72,98.34 v1(71.69,98.31) ; v1(65.88,134.1) 64.61,134.1 63.41,135.29 J5.27
  BOTTOM w0.121: v1(65.88,134.1) 65.88,124.82 66.59,124.12 66.59,121.14 69.93,117.79 69.93,107.23 70.84,106.32 70.84,103 70.08,102.24 70.08,100.63 71.31,99.4 71.31,98.69 v1(71.69,98.31)
EXP_UART1_CTSN: length 41.4
  TOP w0.121: v1(67.86,133.85) 67.85,133.84 66.66,133.84 66.47,133.65 63.22,133.65 60.87,136 J5.29 ; R225.2 v1(74.21,104.94)
  BOTTOM w0.121: v1(67.86,133.85) 68.48,133.22 68.48,124.44 69.16,123.77 69.16,121.93 74.21,116.88 v1(74.21,104.94)
EXP_UART1_RTSN: length 48.7
  TOP w0.121: v1(68.64,133.84) 68.2,133.41 62.83,133.41 60.77,135.47 58.94,135.47 58.33,136.08 J5.31 ; R229.2 v1(75.22,101.26)
  BOTTOM w0.121: v1(75.22,101.26) 74.65,101.83 74.65,105.26 74.45,105.45 74.45,117.33 69.63,122.16 69.63,123.65 68.73,124.54 68.73,133.39 68.64,133.48 v1(68.64,133.84)
EXP_UART1_RXD: length 49.7
  TOP w0.121: J5.33 57.75,135.11 60.33,135.11 62.48,132.96 v1(67.88,132.96) ; R232.2 v1(73.7,100.49)
  BOTTOM w0.121: v1(73.7,100.49) 73.7,101.76 71.16,104.3 71.16,118.04 67.92,121.28 67.92,124.04 68.24,124.36 68.24,132.61 v1(67.88,132.96)
EXP_UART1_TXD: length 57.1
  TOP w0.121: R236.2 75.48,97.7 75.48,98.12 v1(74.86,98.74) ; J5.35 53.25,137.04 55.43,134.86 60.23,134.86 62.57,132.52 69.79,132.52 v1(69.89,132.63)
  BOTTOM w0.121: v1(74.86,98.74) 74.86,99.42 75.73,100.29 75.73,101.37 74.89,102.21 74.89,105.39 74.7,105.59 74.7,117.84 72.04,120.51 72.04,122.84 70.71,124.16 70.71,124.37 70.71,128.57 69.89,129.4 v1(69.89,132.63)
EXP_WAKEUP: length 1.8
  BOTTOM w0.121: R207.1 J5.18
EXP_XDMA_EVENT_INTR0: length 48
  TOP w0.121: R221.1 v1(65.34,96.05)
  BOTTOM w0.121: v1(65.34,96.05) 65.1,96.29 65.1,101.44 64.96,101.58 64.96,101.71 64.96,101.71 64.96,118.66 60.7,122.92 60.7,134.69 62.06,136.05 62.06,138.26 J5.28
EXP_XDMA_EVENT_INTR1: length 52.2
  TOP w0.121: R228.1 65.44,91.99 v1(65.19,92.24)
  BOTTOM w0.121: v1(65.19,92.24) 65.19,93.89 64.37,94.71 64.37,97.26 64.85,97.74 64.85,101.33 64.65,101.53 64.65,114.82 61.45,118.02 61.45,121.43 58.64,124.24 58.64,130.03 58.3,130.36 58.3,134 59.35,135.04 59.35,138.59 J5.32
GPMC_A0: length 7
  TOP w0.121: v1(88.07,123.33) 88.07,123.05 88.66,122.47 R193.1
  LY3 w0.133: v1(88.07,123.33) 86.58,124.82 86.58,127.22 J6.2
GPMC_A1: length 6.3
  TOP w0.121: R196.1 86.22,122.54 86.22,126.96 J6.4
GPMC_A2: length 6.2
  TOP w0.121: J6.6 83.73,126.91 R198.1
GPMC_A3: length 6.2
  TOP w0.121: R202.1 81.19,126.91 J6.8
GPMC_A4: length 39.1
  TOP w0.121: v1(94.63,126.33) 94.58,126.38 91.27,126.38 88.51,129.15 78.32,129.15 77.38,128.21 J6.10 ; v1(91.86,115.43) 92.24,115.05 R206.1
  LY3 w0.133: v1(94.63,126.33) 94.63,122.69 97.89,119.43 97.89,116.74 96.58,115.43 v1(91.86,115.43)
GPMC_A5: length 41
  TOP w0.121: J6.12 74.87,128.18 76.08,129.39 88.74,129.39 91.12,127.01 94.47,127.01 v1(94.6,127.14) ; R209.1 v1(90.97,115.43)
  LY3 w0.133: v1(90.97,115.43) 91.58,116.04 95.13,116.04 95.66,116.56 95.66,119.53 93.84,121.35 93.84,126.86 94.12,127.14 v1(94.6,127.14)
GPMC_A6: length 40.7
  TOP w0.121: v1(92.6,128.74) 92.11,128.25 91.52,128.25 90.1,129.67 71.15,129.67 69.76,128.28 J6.16 ; v1(93.1,113.52) 93.38,113.24 R214.1
  LY4 w0.133: v1(92.6,128.74) 92.6,117.82 92.5,117.72 92.5,114.12 v1(93.1,113.52)
GPMC_A7: length 47.9
  TOP w0.121: R217.1 86.52,114.18 v1(88.53,116.19) ; J6.18 69.02,129.98 90.42,129.98 v1(91.71,128.69)
  LY3 w0.133: v1(91.71,128.69) 91.71,119.52 93.53,117.69 93.53,116.76 93.33,116.56 88.9,116.56 v1(88.53,116.19)
GPMC_A8: length 56
  TOP w0.121: J6.22 64.52,130.56 90.62,130.56 v1(91.73,129.45) ; v1(88.43,115.3) 88.43,113.17 R223.1
  LY3 w0.133: v1(88.43,115.3) 88.76,115.3 89.75,116.3 94.65,116.3 95.35,117 95.35,119.45 93.05,121.76 93.05,129.32 92.92,129.45 v1(91.73,129.45)
GPMC_A9: length 6.9
  TOP w0.121: v1(60.21,129.58) 59.27,129.58 58.84,130.01 57.87,130.01 57.49,129.63 57.49,129.2 58.23,128.46 58.41,128.46 58.69,128.18 J6.24
  BOTTOM w0.121: R226.1 59.6,130.19 v1(60.21,129.58)
GPMC_A10: length 43.1
  TOP w0.121: R230.1 89.34,132.89 v1(89.34,132.88)
  LY3 w0.133: v1(57.06,131.23) 60.46,134.63 70.36,134.63 70.5,134.5 70.5,133.83 70.63,133.69 70.9,133.69 71.03,133.83 71.03,134.5 71.16,134.63 71.43,134.63 71.56,134.5 71.56,133.83 71.7,133.69 71.96,133.69 72.1,133.83 72.1,134.5 72.23,134.63 72.5,134.63 72.63,134.5 72.63,133.83 72.76,133.69 73.03,133.69 73.16,133.83 73.16,134.5 73.3,134.63 75.96,134.63 77.71,132.88 v1(89.34,132.88)
  BOTTOM w0.121: J6.26 v1(57.06,131.23)
GPMC_A11: length 5.2
  LY3 w0.133: v1(55.49,124.27) 55.49,127.21 J6.28
  BOTTOM w0.121: R233.1 56.07,123.68 v1(55.49,124.27)
JTAG_EMU0: length 68.7
  TOP w0.102: v2(79.4,89) U2.C14
  TOP w0.121: v1(22.14,89.19) J2.13 ; v1(70.3,92.85) 70.3,92.73 69.8,92.23 68.52,92.23 67.75,93 66.31,93 66.14,93.18 65.96,93.18 65.46,93.69 64.67,93.69 63.83,94.53 62.14,94.53 60.94,93.32 59.91,93.32 59.28,93.95 57.23,93.95 56.14,92.86 48.45,92.86 47.08,91.5 35.37,91.5 35.17,91.69 v1(34.73,91.69)
  LY3 w0.133: v1(22.14,89.19) 24.98,92.04 24.98,92.98 25.49,93.48 30.16,93.48 31.95,91.69 v1(34.73,91.69)
  BOTTOM w0.102: 78.98,89 v2(79.4,89)
  BOTTOM w0.121: v1(70.3,92.85) 70.3,92.38 73.46,89.23 78.75,89.23 78.98,89 ; R71.1 v1(22.14,89.19)
JTAG_EMU1: length 62.7
  TOP w0.102: U2.B14 78.6,89 77.5,89
  TOP w0.121: v1(31.91,93.76) 32.57,93.76 32.88,93.46 32.88,92.85 33.35,92.38 47.14,92.38 48.11,93.36 55.92,93.36 57.31,94.75 59.45,94.75 60.23,95.53 62.36,95.53 63.08,96.26 64.86,96.26 65.21,96.61 69.56,96.61 69.8,96.36 v1(69.8,96.33) ; J2.14 v1(31.41,89.19) ; 77.5,89 77.21,89 76.96,89.25 76.37,89.25 74.98,90.64 73.6,90.64 73.46,90.78 73.46,91.36 73.07,91.75 v1(73.06,91.75)
  BOTTOM w0.121: R70.1 v1(31.41,89.19) 31.91,89.7 v1(31.91,93.76) ; v1(69.8,96.33) 69.8,95.83 70.11,95.53 70.11,94.36 70.99,93.47 70.99,92.66 71.9,91.75 v1(73.06,91.75)
JTAG_TCK: length 60.4
  TOP w0.102: 77.45,87.3 77.75,87 U2.A12
  TOP w0.121: 77.45,87.3 77.08,87.3 76.36,88.02 75.78,88.02 74.62,89.17 74.4,89.39 74.36,89.39 69.49,89.39 69.49,89.4 69.26,89.4 67.94,90.72 65.63,90.72 65.51,90.84 v1(65.12,90.84) ; v1(63.66,89) 59.85,89 59.1,89.75 56.26,89.75 54.69,91.31 49.03,91.31 47.32,89.6 35.5,89.6 35.3,89.39 v1(34.86,89.39)
  LY3 w0.133: v1(25.95,90.46) 30.44,90.46 31,89.9 34.35,89.9 v1(34.86,89.39)
  BOTTOM w0.121: v1(65.12,90.84) 65.12,90.14 63.98,89 v1(63.66,89) ; v1(25.95,90.46) R75.2 R74.2
JTAG_TDI: length 71.9
  TOP w0.102: U2.B11 78.61,86.59 77.63,86.59 77.3,86.92
  TOP w0.121: J2.3 26.07,95.54 26.45,95.92 26.45,97.32 26.71,97.57 32.02,97.57 32.04,97.6 v1(34.15,97.6) ; 77.3,86.92 76.92,86.92 76.21,87.64 75.62,87.64 74.24,89.02 74.21,89.02 72.26,89.02 71.39,88.15 71.33,88.15 v1(71.02,87.84) ; v1(33.9,88.23) 34.22,87.91 39.37,87.91 40.44,88.98 47.57,88.98 49.29,90.69 54.4,90.69 56.38,88.71 58.81,88.71 59.41,88.11 v1(63.66,88.11)
  BOTTOM w0.121: v1(33.9,88.23) 33.9,88.67 33.84,88.73 33.84,97.29 v1(34.15,97.6) ; v1(71.02,87.84) 71.02,87.64 70.23,86.85 68.69,86.85 66.97,88.58 64.13,88.58 v1(63.66,88.11)
JTAG_TDO: length 60.2
  TOP w0.102: U2.A11 77.45,86.2 77.1,86.55
  TOP w0.121: J2.7 v1(25.95,93) ; v1(34.76,90.56) 35.2,90.56 35.42,90.34 47.01,90.34 48.72,92.05 55.52,92.05 56.92,90.65 61.56,90.65 61.63,90.72 63.39,90.72 64.03,90.08 65.14,90.08 65.14,90.08 65.27,90.08 65.64,90.45 67.85,90.45 69.16,89.15 69.69,89.15 70.58,88.26 70.58,87.58 70.76,87.4 71.27,87.4 72.37,88.5 72.52,88.64 73.64,88.64 74.09,88.64 75.47,87.27 76.05,87.27 76.77,86.55 77.1,86.55
  LY3 w0.133: v1(25.95,93) 30.06,93 32.5,90.56 v1(34.76,90.56)
JTAG_TMS: length 70.7
  TOP w0.102: U2.C11 79.41,86.59 v2(79.41,87.41)
  TOP w0.121: v1(69.07,99.88) 69.03,99.92 68.55,99.92 67.98,99.35 67.22,98.59 64.77,98.59 64.27,98.09 63.7,98.09 63.29,98.49 61.42,98.49 61.05,98.13 56.58,98.13 55.89,98.82 43.22,98.82 42.42,98.03 34.34,98.03 34.33,98.04 33.97,98.04 33.96,98.03 24.64,98.03 24,97.4 J2.1
  LY4 w0.121: 68.87,95.95 68.87,99.61 69.07,99.81 v1(69.07,99.88)
  LY4 w0.133: v1(69.86,91.49) 69.34,90.97 68.87,90.97 68.57,91.27 68.57,92.29 68.87,92.6 68.87,95.95
  BOTTOM w0.102: 77.1,88.48 77.52,88.48 78.59,87.41 v2(79.41,87.41)
  BOTTOM w0.121: v1(69.86,91.49) 70.14,91.49 71.81,89.83 73.15,88.48 77.1,88.48
JTAG_TRSTN: length 63.2
  TOP w0.102: U2.B10 78.82,85.4 78.4,85.83 77.44,85.83 77.1,86.17
  TOP w0.121: v1(34.28,89.05) 34.59,88.74 39.63,88.74 40.24,89.35 47.42,89.35 49.13,91.06 54.56,91.06 56.18,89.45 58.65,89.45 59.53,88.56 63.48,88.56 63.48,88.56 63.85,88.56 64.3,89.02 v1(64.71,89.02) ; 77.1,86.17 76.8,86.17 75.95,87.02 75.36,87.02 73.98,88.4 73.95,88.4 72.62,88.4 71.37,87.15 70.66,87.15 70.51,87.3 70.14,87.67 v1(70.14,87.87) ; J2.2 v1(31.41,96.81) 32.28,96.81 32.29,96.82 32.66,96.82 32.67,96.81 v1(34.28,96.81)
  BOTTOM w0.121: v1(34.28,89.05) 34.28,89.5 34.28,89.5 34.28,96.37 34.28,96.37 v1(34.28,96.81) ; v1(70.14,87.87) 70.13,87.87 68.92,87.87 67.78,89.02 v1(64.71,89.02) ; v1(31.41,96.81) R79.2
LCD_DATA0: length 4.5
  TOP w0.102: 138.01,85.25 J7.4
  TOP w0.121: R240.1 140.12,86.27 140.12,86.42 140.02,86.52 139.07,86.52 138.88,86.34 138.88,86.29 139.1,86.07 139.1,85.94 138.95,85.79 138.54,85.79 138.01,85.25
LCD_DATA1: length 4.7
  TOP w0.102: 138.04,85.91 136.59,85.91 J7.3
  TOP w0.121: 138.04,85.91 138.11,85.91 139.23,87.03 R241.1
LCD_DATA2: length 4.4
  TOP w0.102: J7.6 137.91,83.98 138.04,83.86
  TOP w0.121: R245.1 140.14,83.88 140.14,83.98 140.01,84.11 139.65,84.11 139.63,84.14 139.43,84.14 139.25,83.96 139.25,83.68 139.17,83.6 138.98,83.6 138.85,83.72 138.85,83.83 138.78,83.9 138.61,83.9 138.52,83.81 138.52,83.73 138.39,83.6 138.39,83.6 138.24,83.6 138.06,83.78 138.06,83.83 138.04,83.86
LCD_DATA3: length 4.5
  TOP w0.121: R246.1 139.61,84.87 139.1,84.87 v1(138.72,84.49)
  BOTTOM w0.102: J7.5 136.54,84.59 137.93,84.59 138.04,84.49
  BOTTOM w0.121: v1(138.72,84.49) 138.04,84.49
LCD_DATA4: length 4.5
  TOP w0.102: 138.04,82.16 137.98,82.21 137.98,82.56 137.83,82.71 J7.8
  TOP w0.121: 138.04,82.16 138.18,82.01 138.3,82.01 138.44,82.16 138.63,82.16 138.86,81.93 139,81.93 139.1,82.03 139.1,82.21 139.18,82.28 139.33,82.28 139.53,82.08 140.07,82.08 140.13,82.01 140.13,81.84 R251.1
LCD_DATA5: length 4.5
  TOP w0.121: v1(138.59,82.84) 138.85,82.59 R252.1
  BOTTOM w0.102: 138.04,83.27 137.96,83.35 136.56,83.35 J7.7
  BOTTOM w0.121: 138.04,83.27 138.47,82.84 v1(138.59,82.84)
LCD_DATA6: length 4.5
  TOP w0.102: J8.15 130.67,77.63 130.52,77.79 130.52,78.32
  TOP w0.121: 130.52,78.32 130.39,78.45 130.19,78.45 130.06,78.32 130.06,77.53 129.93,77.41 129.4,77.41 129.27,77.53 129.27,77.63 129.15,77.76 R270.1
LCD_DATA7: length 8.6
  TOP w0.121: R259.1 129.2,82.84 v1(129.49,82.55)
  LY3 w0.102: 130.57,81.44 J8.9
  LY3 w0.133: 130.57,81.44 130.21,81.44 130.09,81.57 130.09,83.2 129.96,83.32 127.88,83.32 127.75,83.2 127.75,82.9 128.1,82.55 v1(129.49,82.55)
LCD_DATA8: length 9.4
  TOP w0.102: 133.59,81.95 133.46,82.08 130.72,82.08 ; 133.59,80.94 133.49,80.83 132.19,80.83 131.53,80.17 J8.11
  TOP w0.121: R262.1 129.53,80.81 130.14,81.42 130.14,81.78 130.26,81.9 130.26,81.9 130.44,82.08 130.72,82.08 ; 133.59,81.95 133.72,81.95 133.84,81.83 133.84,81.14 133.64,80.94 133.59,80.94
LCD_DATA9: length 4.1
  TOP w0.102: J8.13 130.67,78.9 130.54,78.78 129.81,78.78 129.71,78.68 129.71,78.14 129.61,78.04 129.41,78.04 129.31,78.14 129.31,78.68 129.2,78.78 R266.1
LCD_DATA10: length 10.1
  TOP w0.121: R256.1 139.31,79.54 139.18,79.67 139.18,79.91 v1(138.72,80.37)
  LY3 w0.102: J7.10 138.01,81.44 138.14,81.32
  LY3 w0.133: 138.14,81.32 138.47,80.99 139.99,80.99 140.09,80.89 140.09,78.68 139.97,78.55 138.85,78.55 138.72,78.68 v1(138.72,80.37)
LCD_DATA11: length 10.7
  TOP w0.121: R267.1 139.1,77.13 v1(138.89,77.34)
  LY3 w0.102: 141.67,77.91 138.29,77.91 138.01,77.63 J7.16
  LY3 w0.133: 141.67,77.91 141.79,77.79 141.79,76.62 141.67,76.49 139.13,76.49 138.89,76.73 v1(138.89,77.34)
LCD_DATA12: length 13.1
  TOP w0.121: R257.1 139.86,80.94 139.74,81.07 138.46,81.07 138.34,81.19 138.34,81.32 v1(138.59,81.57)
  BOTTOM w0.102: J7.9 136.56,82.08 137.63,82.08 137.97,82.42 138.04,82.42
  BOTTOM w0.121: v1(138.59,81.57) 139.31,81.57 139.51,81.77 139.51,84.62 139.41,84.72 139.27,84.72 139.18,84.62 139.18,82.21 139.05,82.08 138.29,82.08 138.21,82.16 138.21,82.3 138.09,82.42 138.04,82.42
LCD_DATA13: length 18.6
  TOP w0.121: R258.1 129.27,81.83 v1(129.53,81.57)
  LY3 w0.102: 130.72,80.57 130.99,80.83 133.59,80.83 ; J8.10 133.59,81.44
  LY3 w0.133: 130.72,80.57 130.4,80.57 130.26,80.7 130.26,80.83 130.13,80.97 129.37,80.97 128.41,81.93 128.41,82.02 128.54,82.16 128.94,82.16 v1(129.53,81.57) ; 133.59,81.44 133.67,81.52 133.67,84.45 133.79,84.57 133.96,84.57 134.08,84.45 134.08,84.21 134.23,84.06 134.4,84.06 134.53,83.93 134.53,83.11 134.4,82.98 134.28,82.98 134.15,82.85 134.15,82.57 134.28,82.45 134.43,82.45 134.56,82.32 134.56,82.04 134.43,81.91 134.2,81.91 134.07,81.79 134.07,81.51 134.2,81.38 134.38,81.38 134.5,81.25 134.5,80.96 134.38,80.83 133.59,80.83
LCD_DATA14: length 9.2
  TOP w0.102: 138.04,78.87 138.04,78.88 138.04,79.72 ; 138.04,80.17 J7.12
  TOP w0.121: 138.04,79.72 138.16,79.84 138.16,80.05 138.04,80.17 ; R260.1 140.25,78.78 140.25,78.85 140.06,79.03 139.65,79.03 139.57,79.12 139.4,79.12 139.25,78.97 139.25,78.35 139.14,78.24 138.98,78.24 138.87,78.35 138.87,79.72 138.75,79.84 138.57,79.84 138.44,79.72 138.44,78.44 138.33,78.32 138.16,78.32 138.04,78.44 138.04,78.87
LCD_DATA15: length 24.4
  TOP w0.121: R254.1 v1(129.7,83.86)
  LY3 w0.102: J8.7 130.65,82.71 130.55,82.82
  LY3 w0.133: 130.55,82.82 130.42,82.95 130.42,84.49 130.28,84.62 128.29,84.62 128.15,84.75 128.15,85.02 128.29,85.15 130.28,85.15 130.42,85.29 130.42,86.47 130.29,86.6 128.19,86.6 127.93,86.85 127.65,86.85 127.4,86.6 127.14,86.6 127.01,86.47 127.01,86.21 127.14,86.08 129.82,86.08 129.96,85.95 129.96,85.68 129.82,85.55 127.14,85.55 127.01,85.41 127.01,83.98 127.14,83.86 v1(129.7,83.86)
LCD_DATA16: length 64.1
  TOP w0.121: v1(116.34,98.16) 115.89,98.16 115.77,98.28 115.77,98.6 115.89,98.72 119.3,98.72 119.42,98.84 119.42,99.08 119.3,99.2 115.89,99.2 115.77,99.32 115.77,99.49 115.65,99.61 115.41,99.61 115.29,99.49 115.29,98.28 115.17,98.16 114.03,98.16 113.7,97.82 104.17,97.82 102.39,96.04 100.06,96.04 98.64,94.62 98.64,93.69 98.36,93.41 97.53,93.41 R253.1
  LY4 w0.133: v1(116.34,98.16) 116.47,98.03 116.47,96.42 116.34,96.28 115.79,96.28 115.66,96.15 115.66,95.88 115.79,95.75 116.34,95.75 116.47,95.62 116.47,94.75 116.79,94.43 116.79,93.86 116.78,93.84 116.78,87.18 117,86.96 v1(117,86.38)
  BOTTOM w0.102: J8.8 132.7,82.71 132.09,82.1 130.77,82.1 130.72,82.16
  BOTTOM w0.121: v1(117,86.38) 117.26,86.63 126.85,86.63 127.14,86.35 127.14,84.34 127.7,83.78 129.1,83.78 130.72,82.16
LCD_DATA17: length 46.2
  TOP w0.121: v1(118.41,96.07) 117.86,96.62 103.74,96.62 R248.1
  LY4 w0.133: v1(118.41,96.07) 118.41,95.38 118.54,95.24 119.34,95.24 119.47,95.12 119.47,94.84 119.34,94.71 118.54,94.71 118.41,94.58 118.41,94.31 118.54,94.18 119.54,94.18 119.67,94.04 119.67,93.78 119.54,93.64 118.54,93.64 118.41,93.51 118.41,89.95 118.02,89.56 v1(118.02,87.46)
  BOTTOM w0.102: J8.5 131.28,83.98 130.72,84.54 130.72,84.75
  BOTTOM w0.121: v1(118.02,87.46) 118.97,87.46 119.16,87.28 119.52,87.28 119.71,87.46 127.7,87.46 130.03,85.13 130.34,85.13 130.72,84.75
LCD_DATA18: length 53.5
  TOP w0.102: J8.6 132.12,83.35 130.85,83.35 130.72,83.48
  TOP w0.121: R247.1 97.51,88.86 97.52,88.87 97.9,88.87 98,88.78 98.79,88.78 98.92,88.9 v1(98.92,89.04) ; 130.72,83.48 129.75,84.45 128.48,84.45 127.67,85.25 127.67,85.57 127.55,85.69 126.17,85.69 126.05,85.81 126.05,86.06 126.17,86.18 127.55,86.18 127.67,86.3 127.67,87.03 127.55,87.16 126,87.16 125.24,86.4 125.24,86.23 125.57,85.89 125.57,85.72 125.4,85.55 125.23,85.55 124.9,85.89 124.72,85.89 124.55,85.72 124.55,85.55 124.89,85.21 124.89,85.04 124.72,84.87 124.55,84.87 124.21,85.21 124.04,85.21 123.87,85.03 123.87,84.86 124.21,84.53 124.21,84.36 124.04,84.19 123.87,84.19 123.53,84.52 123.36,84.52 123.19,84.35 123.19,84.18 123.53,83.84 123.53,83.67 123.36,83.5 123.19,83.5 122.85,83.84 122.68,83.84 122.4,83.56 114.37,83.56 112.77,81.96 109.55,81.96 108.11,83.4 108.11,85.93 106.78,87.26 v1(106.78,88.24)
  BOTTOM w0.121: v1(98.92,89.04) 104.91,89.04 105.71,88.24 106.77,88.24 v1(106.78,88.24)
